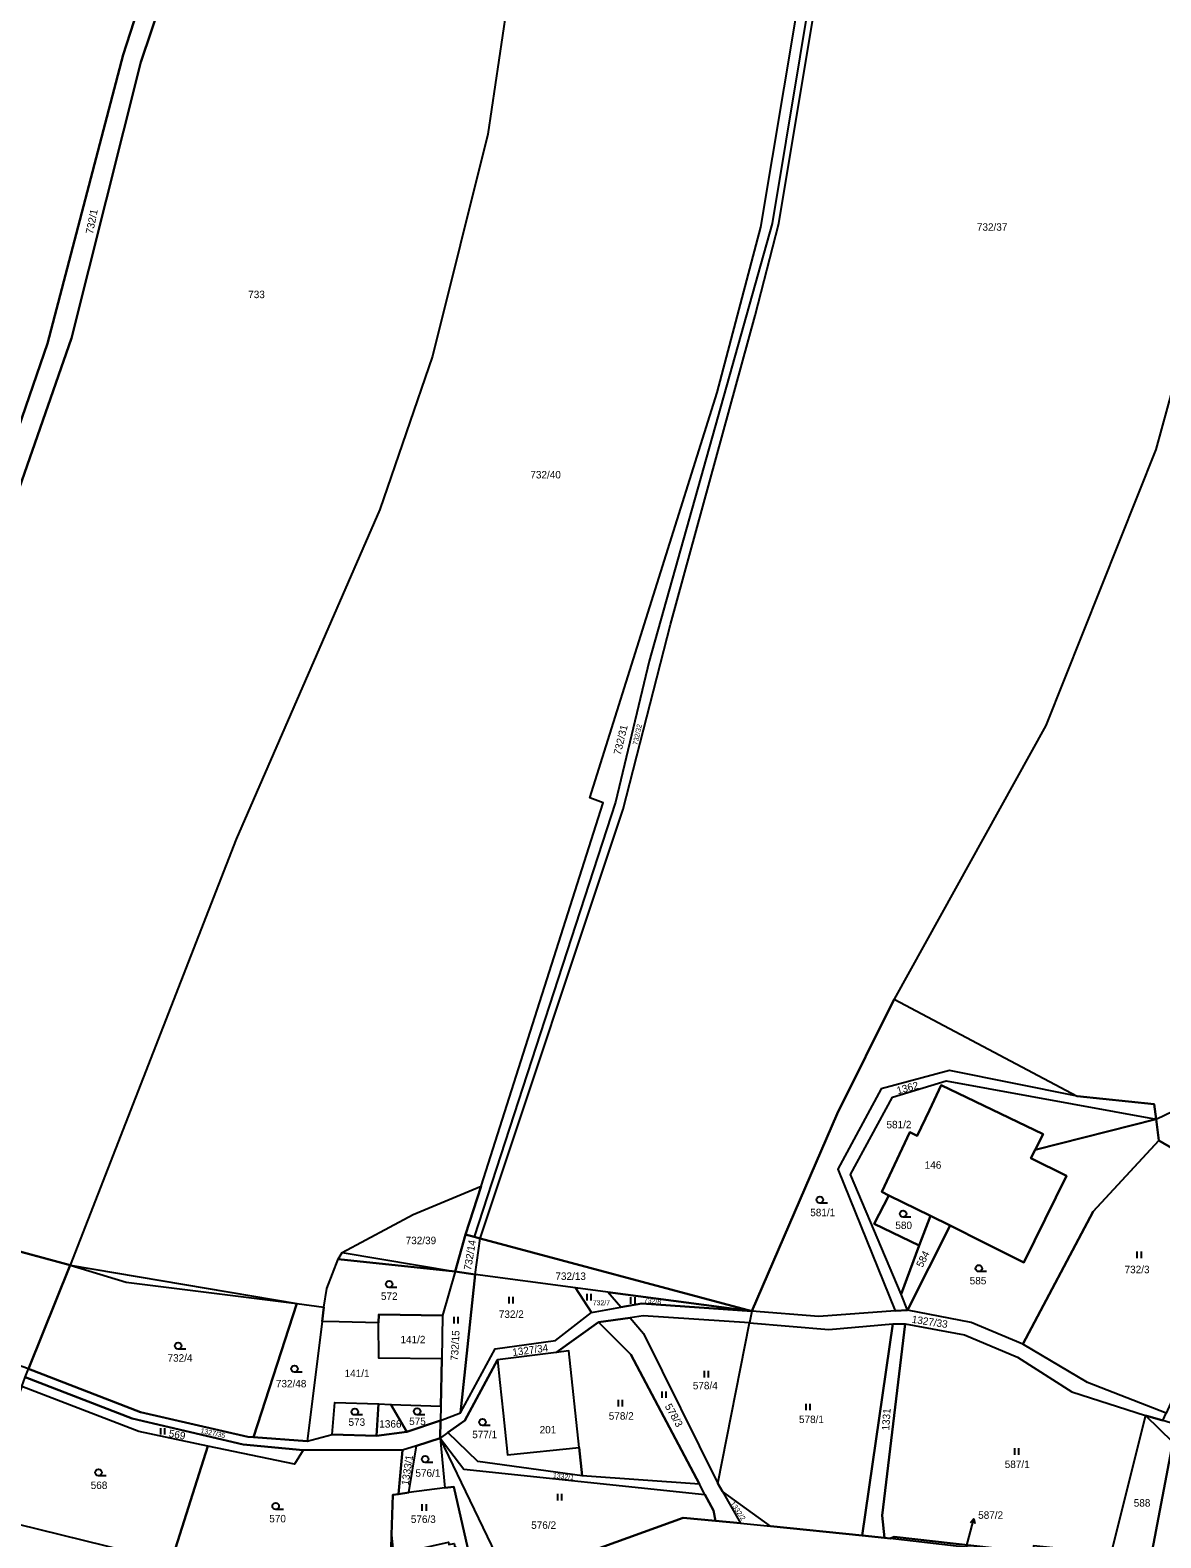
# Model space of a CAD drawing. Extents: x -588699 to -585793, y -1060280 to -1056731.
# Drawn here: x -587129.7 to -586871.9, y -1058550.5 to -1058206.7 of the extents above; entities that cross this region are included whole.
import ezdxf

# ---------------------------------------------------------------- set-up
doc = ezdxf.new("R2010")
doc.units = 0
for name, color, linetype in [('Druh pozemku', 7, 'Continuous'), ('Lesy', 7, 'Continuous'), ('Parcela nároku', 7, 'Continuous'), ('Parcelní číslo', 7, 'Continuous')]:
    doc.layers.add(name, color=color, linetype=linetype)

msp = doc.modelspace()

# ---------------------------------------------------------------- linework, layer by layer
at = {"layer": 'Druh pozemku'}
for p, q in [((-586947.87, -1058474.15), (-586949.62, -1058474.15)), ((-586928.91, -1058477.37), (-586930.66, -1058477.37)), ((-586877.34, -1058485.19), (-586877.34, -1058486.69)), ((-586876.32, -1058486.69), (-586876.32, -1058485.19)), ((-586911.62, -1058489.79), (-586913.37, -1058489.79)), ((-587046.08, -1058493.39), (-587047.83, -1058493.39)), ((-587020.56, -1058495.52), (-587020.56, -1058497.02)), ((-587019.54, -1058497.02), (-587019.54, -1058495.52)), ((-587002.79, -1058494.84), (-587002.79, -1058496.34)), ((-587001.77, -1058496.34), (-587001.77, -1058494.84)), ((-586992.78, -1058495.62), (-586992.78, -1058497.12)), ((-586991.76, -1058497.12), (-586991.76, -1058495.62)), ((-587033.13, -1058500.13), (-587033.13, -1058501.63)), ((-587032.1, -1058501.63), (-587032.1, -1058500.13)), ((-587094.24, -1058507.48), (-587095.99, -1058507.48)), ((-587067.69, -1058512.73), (-587069.44, -1058512.73)), ((-586976.03, -1058512.43), (-586976.03, -1058513.93)), ((-586975.01, -1058513.93), (-586975.01, -1058512.43)), ((-586985.68, -1058517.09), (-586985.68, -1058518.59)), ((-586984.66, -1058518.59), (-586984.66, -1058517.09)), ((-586995.63, -1058519.02), (-586995.63, -1058520.52)), ((-586994.6, -1058520.52), (-586994.6, -1058519.02)), ((-586952.83, -1058519.9), (-586952.83, -1058521.4)), ((-586951.81, -1058521.4), (-586951.81, -1058519.9)), ((-587053.93, -1058522.48), (-587055.68, -1058522.48)), ((-587039.72, -1058522.46), (-587041.47, -1058522.46)), ((-587100.02, -1058525.46), (-587100.02, -1058526.96)), ((-587098.99, -1058526.96), (-587098.99, -1058525.46)), ((-587024.83, -1058524.85), (-587026.58, -1058524.85)), ((-586905.28, -1058530.06), (-586905.28, -1058531.56)), ((-586904.26, -1058531.56), (-586904.26, -1058530.06)), ((-587037.87, -1058533.31), (-587039.62, -1058533.31)), ((-587112.36, -1058536.35), (-587114.11, -1058536.35)), ((-587009.46, -1058540.46), (-587009.46, -1058541.96)), ((-587008.44, -1058541.96), (-587008.44, -1058540.46)), ((-587071.98, -1058544.03), (-587073.73, -1058544.03)), ((-587040.38, -1058542.84), (-587040.38, -1058544.34)), ((-587039.35, -1058544.34), (-587039.35, -1058542.84))]:
    msp.add_line(p, q, dxfattribs=at)
for centre in [(-586949.62, -1058473.4), (-586930.66, -1058476.62), (-586913.37, -1058489.04), (-587047.83, -1058492.64), (-587095.99, -1058506.73), (-587069.44, -1058511.98), (-587055.68, -1058521.73), (-587041.47, -1058521.71), (-587026.58, -1058524.1), (-587114.11, -1058535.6), (-587039.62, -1058532.56), (-587073.73, -1058543.28)]:
    msp.add_circle(centre, 0.75, dxfattribs=at)
at = {"layer": 'Lesy'}
for p, q in [((-586945.7, -1058453.78), (-586932.71, -1058427.7)), ((-586932.71, -1058427.7), (-586890.97, -1058449.75)), ((-586890.97, -1058449.75), (-586873.41, -1058451.57)), ((-586873.41, -1058451.57), (-586872.96, -1058455.04)), ((-586965.12, -1058498.8), (-586945.7, -1058453.78)), ((-586872.96, -1058455.04), (-586872.34, -1058459.88)), ((-586872.34, -1058459.88), (-586849.05, -1058473.39)), ((-587141.1, -1058482.75), (-587120.59, -1058488.29)), ((-587032.83, -1058489.79), (-587030.44, -1058481.33)), ((-587030.44, -1058481.33), (-587028.46, -1058481.86)), ((-587028.46, -1058481.86), (-587027.06, -1058482.23)), ((-587027.06, -1058482.23), (-586965.12, -1058498.8)), ((-587059.5, -1058486.96), (-587058.6, -1058485.46)), ((-587058.6, -1058485.46), (-587032.83, -1058489.79)), ((-587120.59, -1058488.29), (-587068.93, -1058497.09)), ((-587062.08, -1058493.61), (-587059.5, -1058486.96)), ((-587062.73, -1058497.87), (-587062.08, -1058493.61)), ((-587068.93, -1058497.09), (-587062.73, -1058497.87))]:
    msp.add_line(p, q, dxfattribs=at)
at = {"layer": 'Parcela nároku'}
for points in [[(-587093.47, -1058042.85), (-587083.2, -1058085.63), (-587087.45, -1058131.23), (-587096.95, -1058176.54), (-587108.49, -1058212.36), (-587125.77, -1058278.15), (-587153.1, -1058357.53), (-587158, -1058368.22), (-587193.45, -1058428.69), (-587200.12, -1058424.25), (-587247.18, -1058391.8), (-587222.83, -1058325.23), (-587191.01, -1058241.74), (-587172.24, -1058142), (-587169.7, -1058107.61), (-587162.67, -1058067.38), (-587154.26, -1057976.54), (-587133.01, -1057983.57), (-587113.33, -1057983.29)], [(-587108.49, -1058212.36), (-587096.95, -1058176.54), (-587087.45, -1058131.23), (-587083.2, -1058085.63), (-587093.47, -1058042.85), (-587113.33, -1057983.29), (-587108.57, -1057984.69), (-587093.66, -1058027.53), (-587078.98, -1058086.47), (-587083.52, -1058130.86), (-587092.03, -1058176.89), (-587104.48, -1058214.01), (-587120.31, -1058276.98), (-587148.32, -1058357.26), (-587158.27, -1058377.37), (-587191.39, -1058430.39), (-587193.45, -1058428.69), (-587158, -1058368.22), (-587153.1, -1058357.53), (-587125.77, -1058278.15)], [(-586945.17, -1058054.38), (-586939.16, -1058107.31), (-586941.27, -1058129.85), (-586951.11, -1058193.92), (-586960.51, -1058250.82), (-586988.53, -1058350.59), (-586996.22, -1058382.77), (-587028.46, -1058481.86), (-587030.44, -1058481.33), (-587026.88, -1058470.33), (-586999.01, -1058382.92), (-587002.08, -1058381.75), (-586973.08, -1058289.33), (-586963.08, -1058251.63), (-586947.2, -1058156.67), (-586941.09, -1058107.63), (-586947.25, -1058053.86)], [(-586996.22, -1058382.77), (-587028.46, -1058481.86), (-587027.06, -1058482.23), (-586994.52, -1058384.35), (-586983.67, -1058342.24), (-586964.39, -1058271.74), (-586958.96, -1058250.77), (-586941.18, -1058143.96), (-586937.05, -1058107.98), (-586943.35, -1058054.86), (-586945.17, -1058054.38), (-586939.16, -1058107.31), (-586941.27, -1058129.85), (-586951.11, -1058193.92), (-586960.51, -1058250.82), (-586988.53, -1058350.59)], [(-586994.52, -1058384.35), (-586983.67, -1058342.24), (-586964.39, -1058271.74), (-586958.96, -1058250.77), (-586941.18, -1058143.96), (-586937.05, -1058107.98), (-586943.35, -1058054.86), (-586890.81, -1058068.59), (-586877.12, -1058073.9), (-586873.84, -1058067.23), (-586870.41, -1058063.91), (-586831.56, -1058054.99), (-586846.86, -1058152.34), (-586855.66, -1058231.54), (-586862.66, -1058264.6), (-586873.05, -1058302.33), (-586898.07, -1058365.3), (-586932.71, -1058427.7), (-586945.7, -1058453.78), (-586965.12, -1058498.8), (-587027.06, -1058482.23)], [(-586965.12, -1058498.8), (-586945.7, -1058453.78), (-586932.71, -1058427.7), (-586890.97, -1058449.75), (-586920.1, -1058443.93), (-586935.66, -1058448.14), (-586945.53, -1058466.42), (-586932.48, -1058498.76), (-586949.86, -1058500.03)], [(-587187.53, -1058433.57), (-587158.73, -1058464.14), (-587153.29, -1058470.04), (-587149.3, -1058473.77), (-587141.1, -1058482.75), (-587120.59, -1058488.29), (-587130.11, -1058511.95), (-587163.61, -1058500.22), (-587189.74, -1058492.88), (-587187.46, -1058487.29), (-587183.98, -1058478.73), (-587189.54, -1058474.15), (-587177.45, -1058457.99), (-587187.78, -1058450.77), (-587195.93, -1058444.52), (-587199.2, -1058441.97), (-587191.39, -1058430.39)], [(-586920.1, -1058443.93), (-586935.66, -1058448.14), (-586945.53, -1058466.42), (-586932.48, -1058498.76), (-586929.64, -1058498.55), (-586931.11, -1058494.91), (-586942.66, -1058467.61), (-586933.09, -1058450.03), (-586920.81, -1058446.32), (-586872.96, -1058455.04), (-586873.41, -1058451.57), (-586890.97, -1058449.75)], [(-586900.52, -1058462.03), (-586898.7, -1058458.47), (-586921.94, -1058447.3), (-586924.65, -1058452.98), (-586927.42, -1058458.79), (-586929.12, -1058457.97), (-586935.49, -1058471.63), (-586933.91, -1058472.41), (-586937.23, -1058478.88), (-586926.97, -1058483.87), (-586931.11, -1058494.91), (-586942.66, -1058467.61), (-586933.09, -1058450.03), (-586920.81, -1058446.32), (-586872.96, -1058455.04)], [(-586927.42, -1058458.79), (-586924.65, -1058452.98), (-586921.94, -1058447.3), (-586898.7, -1058458.47), (-586900.52, -1058462.03), (-586901.51, -1058463.95), (-586893.38, -1058467.97), (-586903.13, -1058487.68), (-586912.1, -1058483.2), (-586919.91, -1058479.3), (-586924.41, -1058477.05), (-586933.91, -1058472.41), (-586935.49, -1058471.63), (-586929.12, -1058457.97)], [(-586929.64, -1058498.55), (-586919.91, -1058479.3), (-586912.1, -1058483.2), (-586903.13, -1058487.68), (-586893.38, -1058467.97), (-586901.51, -1058463.95), (-586900.52, -1058462.03), (-586872.96, -1058455.04), (-586872.34, -1058459.88), (-586887.34, -1058476.07), (-586903.37, -1058506.33), (-586915.1, -1058501.37)], [(-586887.34, -1058476.07), (-586872.34, -1058459.88), (-586849.05, -1058473.39), (-586858.37, -1058494.54), (-586870.64, -1058522.06), (-586888.56, -1058515.07), (-586903.37, -1058506.33)], [(-587058.6, -1058485.46), (-587042.38, -1058476.73), (-587026.88, -1058470.33), (-587030.44, -1058481.33), (-587032.83, -1058489.79), (-587059.5, -1058486.96)], [(-586933.91, -1058472.41), (-586924.41, -1058477.05), (-586926.97, -1058483.87), (-586937.23, -1058478.88)], [(-586924.41, -1058477.05), (-586919.91, -1058479.3), (-586929.64, -1058498.55), (-586931.11, -1058494.91), (-586926.97, -1058483.87)], [(-587028.46, -1058481.86), (-587030.44, -1058481.33), (-587032.83, -1058489.79), (-587028.24, -1058490.46), (-587027.06, -1058482.23)], [(-587028.24, -1058490.46), (-587027.06, -1058482.23), (-586965.12, -1058498.8), (-586997.99, -1058494.46), (-587005.34, -1058493.49)], [(-587120.59, -1058488.29), (-587107.81, -1058492.23), (-587068.93, -1058497.09), (-587078.81, -1058527.57), (-587080.08, -1058527.48), (-587104.59, -1058521.82), (-587130.11, -1058511.95)], [(-587059.5, -1058486.96), (-587032.83, -1058489.79), (-587035.65, -1058499.76), (-587050.2, -1058499.53), (-587050.26, -1058501.49), (-587059.23, -1058501.24), (-587063.13, -1058501.13), (-587062.73, -1058497.87), (-587062.08, -1058493.61)], [(-587035.65, -1058499.76), (-587035.87, -1058509.7), (-587036.1, -1058520.43), (-587036.17, -1058523.73), (-587031.58, -1058521.98), (-587028.24, -1058490.46), (-587032.83, -1058489.79)], [(-587028.24, -1058490.46), (-587031.58, -1058521.98), (-587023.7, -1058507.4), (-587009.88, -1058505.49), (-587001.73, -1058499.12), (-587005.34, -1058493.49)], [(-586997.99, -1058494.46), (-587005.34, -1058493.49), (-587001.73, -1058499.12), (-586994.99, -1058497.93)], [(-587001.73, -1058499.12), (-586994.99, -1058497.93), (-586990.21, -1058497.08), (-586965.12, -1058498.8), (-586965.65, -1058501.45), (-586989.95, -1058499.89), (-586992.92, -1058500.32), (-587000.14, -1058501.35), (-587009.8, -1058508.22), (-587023.13, -1058509.94), (-587030.59, -1058523.71), (-587034.46, -1058526.47), (-587036.25, -1058527.75), (-587036.17, -1058523.73), (-587031.58, -1058521.98), (-587023.7, -1058507.4), (-587009.88, -1058505.49)], [(-586997.99, -1058494.46), (-586965.12, -1058498.8), (-586990.21, -1058497.08), (-586994.99, -1058497.93)], [(-587078.81, -1058527.57), (-587068.93, -1058497.09), (-587062.73, -1058497.87), (-587063.13, -1058501.13), (-587066.52, -1058528.46)], [(-587050.2, -1058499.53), (-587035.65, -1058499.76), (-587035.87, -1058509.7), (-587050.23, -1058509.54), (-587050.26, -1058501.49)], [(-587000.14, -1058501.35), (-586992.92, -1058500.32), (-586989.82, -1058503.9), (-586972.87, -1058538.08), (-586971.81, -1058539.96), (-586967.76, -1058547.15), (-586973.4, -1058546.58), (-586973.92, -1058544.26), (-586975.85, -1058540.62), (-586977.11, -1058538.24), (-586992.76, -1058508.68)], [(-586965.65, -1058501.45), (-586989.95, -1058499.89), (-586992.92, -1058500.32), (-586989.82, -1058503.9), (-586972.87, -1058538.08)], [(-586870.64, -1058522.06), (-586888.56, -1058515.07), (-586903.37, -1058506.33), (-586915.1, -1058501.37), (-586929.64, -1058498.55), (-586932.48, -1058498.76), (-586949.86, -1058500.03), (-586965.12, -1058498.8), (-586965.65, -1058501.45), (-586947.62, -1058502.97), (-586932.97, -1058501.67), (-586930.16, -1058501.68), (-586916.68, -1058504.17), (-586904.54, -1058509.26), (-586892.17, -1058517.22), (-586875.35, -1058522.58), (-586871.4, -1058523.77)], [(-587059.23, -1058501.24), (-587063.13, -1058501.13), (-587066.52, -1058528.46), (-587060.81, -1058526.91), (-587060.25, -1058519.61), (-587050.27, -1058519.95), (-587047.46, -1058520.05), (-587036.1, -1058520.43), (-587035.87, -1058509.7), (-587050.23, -1058509.54), (-587050.26, -1058501.49)], [(-587000.14, -1058501.35), (-586992.76, -1058508.68), (-586977.11, -1058538.24), (-587003.87, -1058536.35), (-587004.55, -1058529.86), (-587006.86, -1058507.84), (-587009.8, -1058508.22)], [(-586965.65, -1058501.45), (-586947.62, -1058502.97), (-586932.97, -1058501.67), (-586940.02, -1058549.96), (-586960.85, -1058547.85), (-586971.81, -1058539.96), (-586972.87, -1058538.08)], [(-586932.97, -1058501.67), (-586930.16, -1058501.68), (-586935.39, -1058545.43), (-586934.89, -1058550.47), (-586940.02, -1058549.96)], [(-586935.39, -1058545.43), (-586930.16, -1058501.68), (-586916.68, -1058504.17), (-586904.54, -1058509.26), (-586892.17, -1058517.22), (-586875.35, -1058522.58), (-586883.25, -1058554.1), (-586900.89, -1058552.29), (-586901.09, -1058553.82), (-586932.71, -1058550.27), (-586933.62, -1058550.62), (-586934.89, -1058550.47)], [(-587034.46, -1058526.47), (-587030.59, -1058523.71), (-587023.13, -1058509.94), (-587022.6, -1058515.05), (-587021.86, -1058522.1), (-587020.85, -1058531.56), (-587004.55, -1058529.86), (-587003.87, -1058536.35), (-587027.66, -1058533.12)], [(-587009.8, -1058508.22), (-587023.13, -1058509.94), (-587022.6, -1058515.05), (-587021.86, -1058522.1), (-587020.85, -1058531.56), (-587004.55, -1058529.86), (-587006.86, -1058507.84)], [(-587131.64, -1058515.97), (-587130.85, -1058513.89), (-587106.45, -1058523.25), (-587081.17, -1058529.23), (-587067.44, -1058530.49), (-587069.45, -1058533.67), (-587089.18, -1058529.55), (-587104.92, -1058526.27)], [(-587130.85, -1058513.89), (-587130.11, -1058511.95), (-587104.59, -1058521.82), (-587080.08, -1058527.48), (-587078.81, -1058527.57), (-587066.52, -1058528.46), (-587060.81, -1058526.91), (-587050.75, -1058527.22), (-587043.8, -1058526.3), (-587036.17, -1058523.73), (-587036.25, -1058527.75), (-587041.6, -1058529.5), (-587044.77, -1058530.53), (-587067.44, -1058530.49), (-587081.17, -1058529.23), (-587106.45, -1058523.25)], [(-587104.92, -1058526.27), (-587131.64, -1058515.97), (-587142.7, -1058544.9), (-587097.55, -1058555.98), (-587089.18, -1058529.55)], [(-587060.25, -1058519.61), (-587050.27, -1058519.95), (-587050.75, -1058527.22), (-587060.81, -1058526.91)], [(-587050.75, -1058527.22), (-587050.27, -1058519.95), (-587047.46, -1058520.05), (-587043.8, -1058526.3)], [(-587047.46, -1058520.05), (-587036.1, -1058520.43), (-587036.17, -1058523.73), (-587043.8, -1058526.3)], [(-586869.14, -1058528.69), (-586875.35, -1058522.58), (-586883.25, -1058554.1), (-586874.19, -1058555.03)], [(-586871.4, -1058523.77), (-586875.35, -1058522.58), (-586869.14, -1058528.69), (-586874.19, -1058555.03), (-586862.54, -1058558.15), (-586854.02, -1058560.42), (-586804.23, -1058567.06), (-586807.28, -1058561.54), (-586832.56, -1058558.16), (-586845.52, -1058535.63), (-586863.45, -1058526.16)], [(-587020.53, -1058560.29), (-587036.25, -1058527.75), (-587035.15, -1058539.11), (-587033.07, -1058538.84), (-587027.98, -1058561.26), (-587031.82, -1058562.49), (-587030.73, -1058565.03), (-587041.01, -1058569.47), (-587041.81, -1058567.52), (-587044.3, -1058568.61), (-587043.2, -1058571.34), (-587029.94, -1058566.6), (-587022.5, -1058561)], [(-587041.6, -1058529.5), (-587036.25, -1058527.75), (-587035.15, -1058539.11), (-587043.35, -1058540.19)], [(-587003.87, -1058536.35), (-587027.66, -1058533.12), (-587034.46, -1058526.47), (-587036.25, -1058527.75), (-587030.79, -1058534.84), (-586975.85, -1058540.62), (-586977.11, -1058538.24)], [(-587030.79, -1058534.84), (-586975.85, -1058540.62), (-586973.92, -1058544.26), (-586973.4, -1058546.58), (-586980.8, -1058545.9), (-587020.53, -1058560.29), (-587036.25, -1058527.75)], [(-587067.44, -1058530.49), (-587069.45, -1058533.67), (-587089.18, -1058529.55), (-587097.55, -1058555.98), (-587083, -1058560.66), (-587047.58, -1058559.53), (-587047.29, -1058549.84), (-587047.01, -1058540.68), (-587045.74, -1058540.51), (-587044.77, -1058530.53)], [(-587041.6, -1058529.5), (-587044.77, -1058530.53), (-587045.74, -1058540.51), (-587043.35, -1058540.19)], [(-587032.88, -1058557.76), (-587033.76, -1058557.97), (-587031.82, -1058562.49), (-587027.98, -1058561.26), (-587033.07, -1058538.84), (-587035.15, -1058539.11), (-587043.35, -1058540.19), (-587045.74, -1058540.51), (-587047.01, -1058540.68), (-587047.29, -1058549.84), (-587045.93, -1058563.56), (-587043.94, -1058562.68), (-587044.76, -1058560.81), (-587040.45, -1058558.95), (-587041.8, -1058553.15), (-587034.33, -1058551.49), (-587034.21, -1058552.03), (-587033.03, -1058551.76), (-587032.84, -1058552.6), (-587032.67, -1058552.53), (-587031.68, -1058557.38)], [(-586960.85, -1058547.85), (-586971.81, -1058539.96), (-586967.76, -1058547.15)], [(-587148.16, -1058564.51), (-587142.7, -1058544.9), (-587097.55, -1058555.98), (-587083, -1058560.66), (-587047.58, -1058559.53), (-587047.89, -1058564.7), (-587046, -1058572.34), (-587055.26, -1058575.46), (-587107.59, -1058563.12), (-587110.09, -1058575.51), (-587116.69, -1058572.64)], [(-587045.06, -1058566.74), (-587044.3, -1058568.61), (-587043.2, -1058571.34), (-587046, -1058572.34), (-587047.89, -1058564.7), (-587047.58, -1058559.53), (-587047.29, -1058549.84), (-587045.93, -1058563.56), (-587045.8, -1058564.89)], [(-586901.09, -1058553.82), (-586874.54, -1058556.8), (-586874.68, -1058557.5), (-586933.62, -1058550.62), (-586932.71, -1058550.27)]]:
    msp.add_lwpolyline(points, close=True, dxfattribs=at)
for points in [[(-587148.32, -1058357.26), (-587120.31, -1058276.98), (-587104.48, -1058214.01), (-587092.03, -1058176.89), (-587083.52, -1058130.86), (-587078.98, -1058086.47), (-587093.66, -1058027.53), (-587108.57, -1057984.69), (-587098.26, -1057988.35), (-587074.72, -1058011.8), (-587055.22, -1058026.64), (-587048.36, -1058039), (-587018.13, -1058067.3), (-587021.38, -1058110.94), (-587019.13, -1058132.51), (-587014.51, -1058157.25), (-587025.35, -1058230.42), (-587037.95, -1058281.07), (-587049.98, -1058316), (-587082.75, -1058391.16), (-587120.59, -1058488.29), (-587141.1, -1058482.75)], [(-586846.86, -1058152.34), (-586855.66, -1058231.54), (-586862.66, -1058264.6), (-586873.05, -1058302.33), (-586898.07, -1058365.3), (-586932.71, -1058427.7), (-586890.97, -1058449.75), (-586873.41, -1058451.57), (-586872.96, -1058455.04), (-586861.05, -1058449.3), (-586843.65, -1058430.72), (-586816.48, -1058376.75), (-586784.22, -1058303.8), (-586769.76, -1058238.68), (-586742.78, -1058072.26)], [(-586692.92, -1058199.18), (-586696.6, -1058216.99), (-586697.29, -1058236.71), (-586700.08, -1058256.8), (-586708.84, -1058295.17), (-586725.03, -1058364.59), (-586738.13, -1058397.8), (-586756.85, -1058429.23), (-586793.21, -1058497.99), (-586816.44, -1058488.16), (-586823.98, -1058484.75), (-586849.05, -1058473.39), (-586872.34, -1058459.88), (-586872.96, -1058455.04), (-586861.05, -1058449.3), (-586843.65, -1058430.72), (-586816.48, -1058376.75), (-586784.22, -1058303.8), (-586769.76, -1058238.68), (-586742.78, -1058072.26)], [(-587014.51, -1058157.25), (-587025.35, -1058230.42), (-587037.95, -1058281.07), (-587049.98, -1058316), (-587082.75, -1058391.16), (-587120.59, -1058488.29), (-587107.81, -1058492.23), (-587068.93, -1058497.09), (-587062.73, -1058497.87), (-587062.08, -1058493.61), (-587059.5, -1058486.96), (-587058.6, -1058485.46), (-587042.38, -1058476.73), (-587026.88, -1058470.33), (-586999.01, -1058382.92), (-587002.08, -1058381.75), (-586973.08, -1058289.33), (-586963.08, -1058251.63), (-586947.2, -1058156.67)], [(-587020.53, -1058560.29), (-586980.8, -1058545.9), (-586973.4, -1058546.58), (-586967.76, -1058547.15), (-586960.85, -1058547.85), (-586940.02, -1058549.96), (-586934.89, -1058550.47), (-586933.62, -1058550.62)]]:
    msp.add_lwpolyline(points, dxfattribs=at)
at = {"layer": 'Parcelní číslo'}
for p, q in [((-586915.3, -1058549.05), (-586914.53, -1058546.15)), ((-586916.21, -1058552.46), (-586915.3, -1058549.05))]:
    msp.add_line(p, q, dxfattribs=at)
msp.add_lwpolyline([(-586915.27, -1058546.99), (-586914.53, -1058546.15), (-586914.3, -1058547.25)], dxfattribs=at)

# ---------------------------------------------------------------- texts
at = {"layer": 'Parcela nároku'}
for s, height, rotation, p in [('732/1', 1.7, 78.6127, (-587115.41, -1058253.3)), ('732/31', 1.7, 76.2585, (-586995.06, -1058372.1)), ('732/32', 1.14, 77.4976, (-586991.23, -1058369.81)), ('1362', 1.7, 15.4293, (-586931.85, -1058449.38)), ('732/14', 1.7, 80.6666, (-587029.17, -1058489.58)), ('584', 1.7, 63.3668, (-586926.24, -1058489)), ('732/8', 1.14, 353.7107, (-586989.8, -1058496.81)), ('1327/33', 1.7, 351.4693, (-586928.75, -1058501.45)), ('732/15', 1.7, 87.0233, (-587032.15, -1058510.17)), ('1327/34', 1.7, 7.6404, (-587019.64, -1058509.05)), ('578/3', 1.7, 299.6184, (-586985.06, -1058520.49)), ('1331', 1.7, 86.2567, (-586933.81, -1058526.07)), ('569', 1.7, 350.0587, (-587098.21, -1058527.47)), ('1327/35', 1.14, 347.9053, (-587090.92, -1058526.57)), ('1333/1', 1.7, 81.3362, (-587043.42, -1058538.61)), ('1332/1', 1.14, 353.7967, (-587010.55, -1058536.82)), ('1332/2', 1.14, 303.9687, (-586970.12, -1058542.66))]:
    msp.add_text(s, height=height, rotation=rotation, dxfattribs=at).set_placement(p)
for s, height, p in [('732/37', 1.7, (-586913.82, -1058252.45)), ('733', 1.7, (-587079.99, -1058267.82)), ('732/40', 1.7, (-587015.65, -1058308.93)), ('581/2', 1.7, (-586934.44, -1058457.11)), ('146', 1.7, (-586925.72, -1058466.33)), ('581/1', 1.7, (-586951.82, -1058477.15)), ('580', 1.7, (-586932.41, -1058480.08)), ('732/39', 1.7, (-587044.08, -1058483.53)), ('732/13', 1.7, (-587009.94, -1058491.68)), ('732/3', 1.7, (-586880.14, -1058490.15)), ('585', 1.7, (-586915.46, -1058492.7)), ('572', 1.7, (-587049.73, -1058496.24)), ('732/7', 1.14, (-587001.42, -1058497.46)), ('732/2', 1.7, (-587022.84, -1058500.34)), ('141/2', 1.7, (-587045.27, -1058506.13)), ('732/4', 1.7, (-587098.39, -1058510.32)), ('141/1', 1.7, (-587058.01, -1058513.83)), ('732/48', 1.7, (-587073.68, -1058516.18)), ('578/4', 1.7, (-586978.6, -1058516.62)), ('573', 1.7, (-587057.12, -1058524.95)), ('1366', 1.7, (-587050.1, -1058525.36)), ('575', 1.7, (-587043.29, -1058524.77)), ('578/2', 1.7, (-586997.77, -1058523.54)), ('578/1', 1.7, (-586954.39, -1058524.32)), ('577/1', 1.7, (-587028.91, -1058527.77)), ('201', 1.7, (-587013.53, -1058526.68)), ('576/1', 1.7, (-587041.86, -1058536.56)), ('587/1', 1.7, (-586907.47, -1058534.57)), ('568', 1.7, (-587115.91, -1058539.35)), ('588', 1.7, (-586878.05, -1058543.37)), ('570', 1.7, (-587075.19, -1058546.96)), ('576/3', 1.7, (-587042.91, -1058547.09)), ('576/2', 1.7, (-587015.46, -1058548.44))]:
    msp.add_text(s, height=height, dxfattribs=at).set_placement(p)
at = {"layer": 'Parcelní číslo'}
msp.add_text('587/2', height=1.7, dxfattribs=at).set_placement((-586913.53, -1058546.15))

doc.saveas('drawing.dxf')
